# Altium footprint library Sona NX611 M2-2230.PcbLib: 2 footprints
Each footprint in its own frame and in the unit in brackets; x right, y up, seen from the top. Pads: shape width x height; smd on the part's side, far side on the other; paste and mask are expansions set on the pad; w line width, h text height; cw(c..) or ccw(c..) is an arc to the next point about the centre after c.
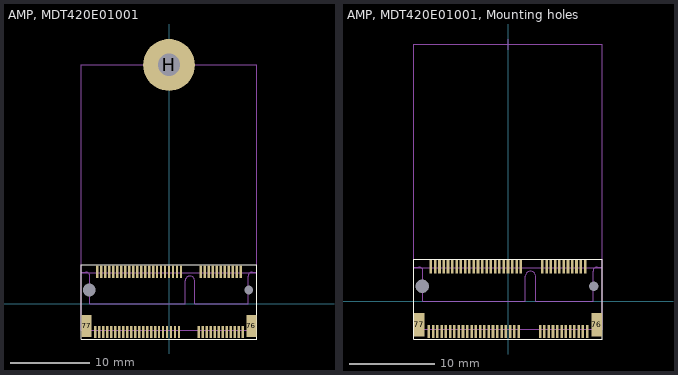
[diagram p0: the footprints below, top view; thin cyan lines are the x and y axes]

## AMP, MDT420E01001 [mm] "AMP, MDT420E01001, M2, Key-E,"
pads (72):
  round 0 hole 1.6 unplated mask+0.051: 1(-10,1.75)
  rect 0.3x1.55 smd mask+0.051: 1(9.25,-3.525) 2(9,4.025) 3(8.75,-3.525) 4(8.5,4.025) 5(8.25,-3.525) 6(8,4.025) 7(7.75,-3.525) 8(7.5,4.025) 9(7.25,-3.525) 10(7,4.025) 11(6.75,-3.525) 12(6.5,4.025) 13(6.25,-3.525) 14(6,4.025) 15(5.75,-3.525) 16(5.5,4.025) 17(5.25,-3.525) 18(5,4.025) 19(4.75,-3.525) 20(4.5,4.025) 21(4.25,-3.525) 22(4,4.025) 23(3.75,-3.525) 32(1.5,4.025) 33(1.25,-3.525) 34(1,4.025) 35(0.75,-3.525) 36(0.5,4.025) 37(0.25,-3.525) 38(0,4.025) 39(-0.25,-3.525) 40(-0.5,4.025) 41(-0.75,-3.525) 42(-1,4.025) 43(-1.25,-3.525) 44(-1.5,4.025) 45(-1.75,-3.525) 46(-2,4.025) 47(-2.25,-3.525) 48(-2.5,4.025) 49(-2.75,-3.525) 50(-3,4.025) 51(-3.25,-3.525) 52(-3.5,4.025) 53(-3.75,-3.525) 54(-4,4.025) 55(-4.25,-3.525) 56(-4.5,4.025) 57(-4.75,-3.525) 58(-5,4.025) 59(-5.25,-3.525) 60(-5.5,4.025) 61(-5.75,-3.525) 62(-6,4.025) 63(-6.25,-3.525) 64(-6.5,4.025) 65(-6.75,-3.525) 66(-7,4.025) 67(-7.25,-3.525) 68(-7.5,4.025) 69(-7.75,-3.525) 70(-8,4.025) 71(-8.25,-3.525) 72(-8.5,4.025) 73(-8.75,-3.525) 74(-9,4.025) 75(-9.25,-3.525)
  round 0 hole 1.1 unplated mask+0.051: 1(10,1.75)
  rect 1.2x2.75 smd mask+0.051: 76(10.35,-2.75) 77(-10.35,-2.75)
  round 6.5 hole 2.8 paste-2539.97 mask+0.051: H(0,30)
Top Overlay:
  lines w0.127: -11,-4.4 -11,4.9 11,4.9 11,-4.4 -11,-4.4
Top Top Assembly/Bottom Assembly:
  lines w0.025: -11,-3.28 11,-3.28 11,3.92 -11,3.92 -11,-3.28
  lines w0.102: -11,4 -10.425,4 cw(c-10.425,3.5) -9.925,3.5 -9.925,0 2.025,0 2.025,2.9 cw(c2.625,2.9) 2.625,3.5 cw(c2.625,2.9) 3.225,2.9 3.225,0 7.225,0 9.925,0 9.925,3.5 cw(c10.425,3.5) 10.425,4 11,4 11,30 -11,30 -11,4
  text ".Designator" at 2.3,0.2 h0.6
3D body "M-mdt420e0x001-REVG1.STEP": height 4.21, standoff -0.59, extent -11,-3.95 11,4.6

## AMP, MDT420E01001, Mounting holes [mm] "AMP, MDT420E01001, M2, Key-E, w/Mounting holes"
pads (71):
  rect 0.3x1.55 smd mask+0.051: 1(9.25,-3.525) 2(9,4.025) 3(8.75,-3.525) 4(8.5,4.025) 5(8.25,-3.525) 6(8,4.025) 7(7.75,-3.525) 8(7.5,4.025) 9(7.25,-3.525) 10(7,4.025) 11(6.75,-3.525) 12(6.5,4.025) 13(6.25,-3.525) 14(6,4.025) 15(5.75,-3.525) 16(5.5,4.025) 17(5.25,-3.525) 18(5,4.025) 19(4.75,-3.525) 20(4.5,4.025) 21(4.25,-3.525) 22(4,4.025) 23(3.75,-3.525) 32(1.5,4.025) 33(1.25,-3.525) 34(1,4.025) 35(0.75,-3.525) 36(0.5,4.025) 37(0.25,-3.525) 38(0,4.025) 39(-0.25,-3.525) 40(-0.5,4.025) 41(-0.75,-3.525) 42(-1,4.025) 43(-1.25,-3.525) 44(-1.5,4.025) 45(-1.75,-3.525) 46(-2,4.025) 47(-2.25,-3.525) 48(-2.5,4.025) 49(-2.75,-3.525) 50(-3,4.025) 51(-3.25,-3.525) 52(-3.5,4.025) 53(-3.75,-3.525) 54(-4,4.025) 55(-4.25,-3.525) 56(-4.5,4.025) 57(-4.75,-3.525) 58(-5,4.025) 59(-5.25,-3.525) 60(-5.5,4.025) 61(-5.75,-3.525) 62(-6,4.025) 63(-6.25,-3.525) 64(-6.5,4.025) 65(-6.75,-3.525) 66(-7,4.025) 67(-7.25,-3.525) 68(-7.5,4.025) 69(-7.75,-3.525) 70(-8,4.025) 71(-8.25,-3.525) 72(-8.5,4.025) 73(-8.75,-3.525) 74(-9,4.025) 75(-9.25,-3.525)
  rect 1.2x2.75 smd mask+0.051: 76(10.35,-2.75) 77(-10.35,-2.75)
  round 0 hole 1.6 unplated mask+0.051: NC(-10,1.75)
  round 0 hole 1.1 unplated mask+0.051: NC(10,1.75)
Top Overlay:
  lines w0.127: -11,-4.4 11,-4.4 11,4.9 -11,4.9 -11,-4.4
Top Top Assembly/Bottom Assembly:
  lines w0.025: -11,-3.28 -11,3.92 11,3.92 11,-3.28 -11,-3.28
  lines w0.102: -11,4 -11,30 11,30 11,4 10.425,4 ccw(c10.425,3.5) 9.925,3.5 9.925,0 7.225,0 3.225,0 3.225,2.9 ccw(c2.625,2.9) 2.625,3.5 ccw(c2.625,2.9) 2.025,2.9 2.025,0 -9.925,0 -9.925,3.5 ccw(c-10.425,3.5) -10.425,4 -11,4
  lines w0.127: -0.62,30 0.62,30 ; 0,29.38 0,30.62
  text ".Designator" at 2.3,0.2 h0.6
3D body "M-mdt420e0x001-REVG1.STEP": height 4.21, standoff -0.59, extent -11,-3.95 11,4.6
